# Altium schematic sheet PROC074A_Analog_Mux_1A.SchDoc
size 431 x 279 mm; Date: Not shown in title block; ApprovedBy: Not shown in title block; CheckedBy: Not shown in title block; Author: Not shown in title block; CompanyName: Not shown in title block; Engineer: Not shown in title block; Organization: Not shown in title block; Address1: Not shown in title block; Address2: Not shown in title block; Address3: Not shown in title block; Address4: Not shown in title block; DocumentNumber: 1; Revision: Use project parameter SCH_Rev; SheetNumber: 19; SheetTotal: 22; PageSetup: Record=PageOptions¦CenterHorizontal=True¦CenterVertical=True¦PrintScale=1.00¦XCorrection=1.00¦YCorrection=1.00¦PrintKind=0¦BorderSize=5000000¦LeftOffset=0¦BottomOffset=0¦Orientation=2¦PaperLength=1000¦PaperWidth=1000¦Scale=100¦PaperSource=15¦PrintQuality=600¦MediaType=1¦DitherType=10¦PaperKind=Letter¦PrintScaleMode=1
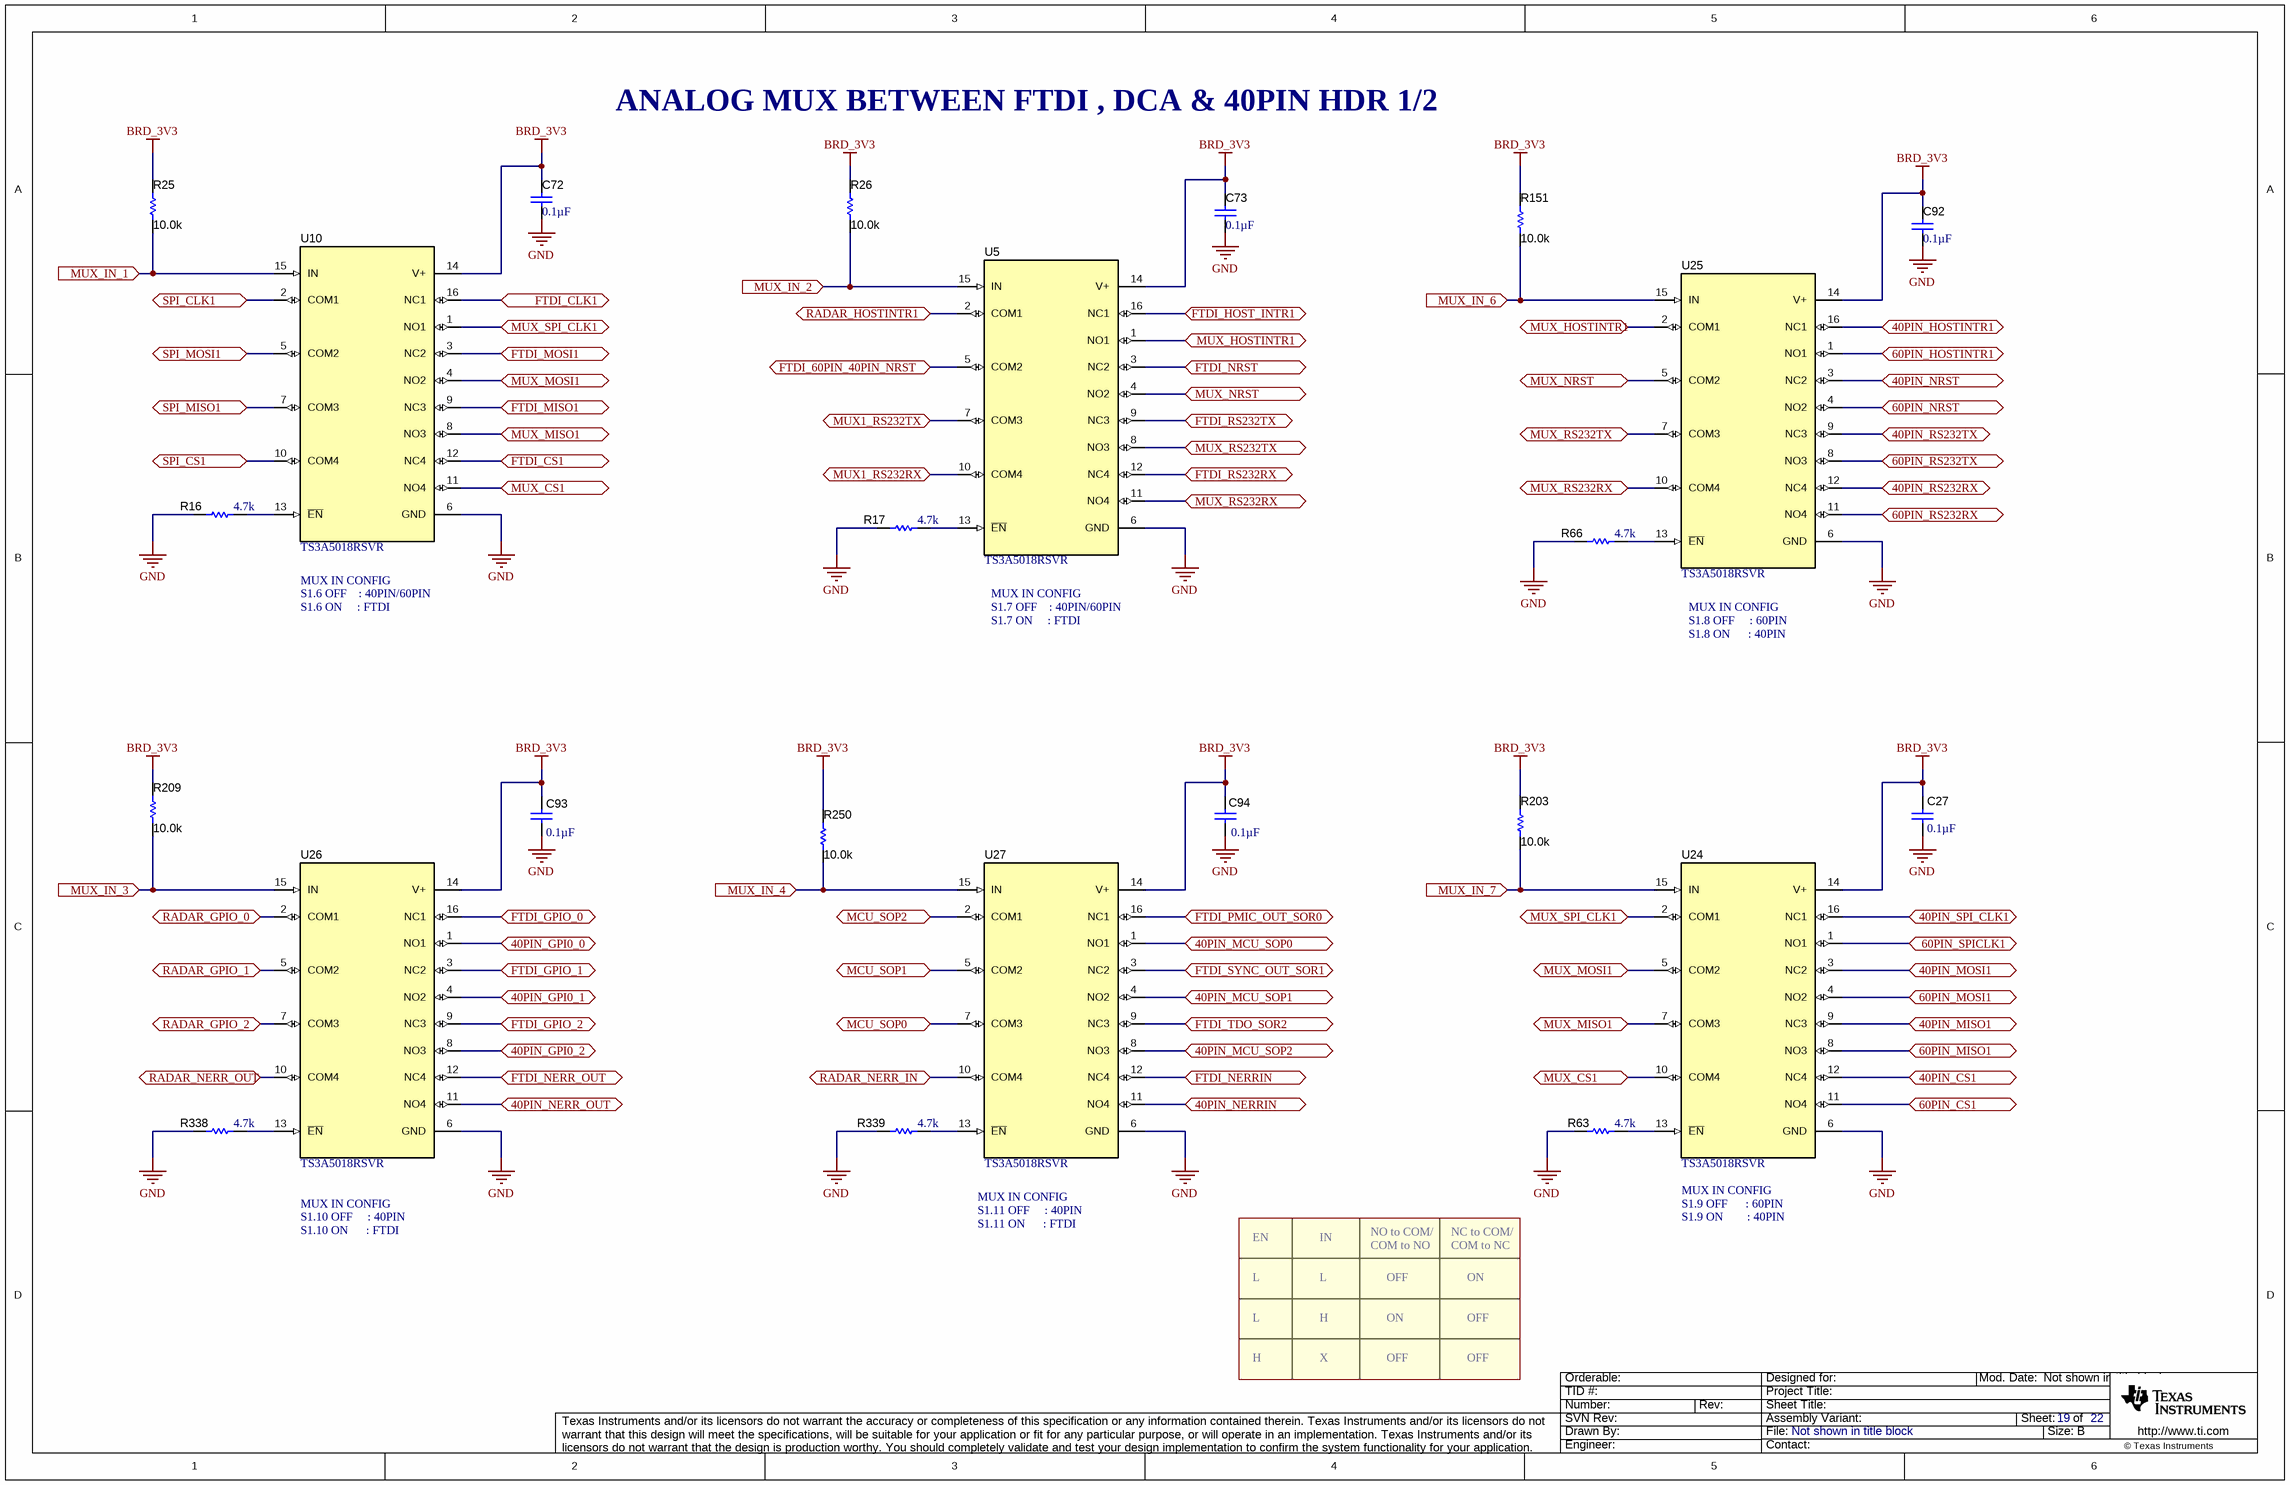
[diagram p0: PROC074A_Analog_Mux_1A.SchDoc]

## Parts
C27  ValueDisplayed: 0.1µF  [0402]  (hidden comment: C0402C104K8RACTU)
C72  ValueDisplayed: 0.1µF  [0402]  (hidden comment: C0402C104K8RACTU)
C73  ValueDisplayed: 0.1µF  [0402]  (hidden comment: C0402C104K8RACTU)
C92  ValueDisplayed: 0.1µF  [0402]  (hidden comment: C0402C104K8RACTU)
C93  ValueDisplayed: 0.1µF  [0402]  (hidden comment: C0402C104K8RACTU)
C94  ValueDisplayed: 0.1µF  [0402]  (hidden comment: C0402C104K8RACTU)
R16  ValueDisplayed: 4.7k  [0402]  (hidden comment: CRCW04024K70JNED)
R17  ValueDisplayed: 4.7k  [0402]  (hidden comment: CRCW04024K70JNED)
R25  ValueDisplayed: 10.0k  [0402L]  (hidden comment: CRCW040210K0FKED)
R26  ValueDisplayed: 10.0k  [0402L]  (hidden comment: CRCW040210K0FKED)
R63  ValueDisplayed: 4.7k  [0402]  (hidden comment: CRCW04024K70JNED)
R66  ValueDisplayed: 4.7k  [0402]  (hidden comment: CRCW04024K70JNED)
R151  ValueDisplayed: 10.0k  [0402L]  (hidden comment: CRCW040210K0FKED)
R203  ValueDisplayed: 10.0k  [0402L]  (hidden comment: CRCW040210K0FKED)
R209  ValueDisplayed: 10.0k  [0402L]  (hidden comment: CRCW040210K0FKED)
R250  ValueDisplayed: 10.0k  [0402L]  (hidden comment: CRCW040210K0FKED)
R338  ValueDisplayed: 4.7k  [0402]  (hidden comment: CRCW04024K70JNED)
R339  ValueDisplayed: 4.7k  [0402]  (hidden comment: CRCW04024K70JNED)
U5  TS3A5018RSVR  [RSV0016A]
U10  TS3A5018RSVR  [RSV0016A]
U24  TS3A5018RSVR  [RSV0016A]
U25  TS3A5018RSVR  [RSV0016A]
U26  TS3A5018RSVR  [RSV0016A]
U27  TS3A5018RSVR  [RSV0016A]

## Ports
40PIN_CS1, 40PIN_GPI0_0, 40PIN_GPI0_1, 40PIN_GPI0_2, 40PIN_HOSTINTR1, 40PIN_MCU_SOP0, 40PIN_MCU_SOP1, 40PIN_MCU_SOP2, 40PIN_MISO1, 40PIN_MOSI1, 40PIN_NERR_OUT, 40PIN_NERRIN, 40PIN_NRST, 40PIN_RS232RX, 40PIN_RS232TX, 40PIN_SPI_CLK1, 60PIN_CS1, 60PIN_HOSTINTR1, 60PIN_MISO1, 60PIN_MOSI1, 60PIN_NRST, 60PIN_RS232RX, 60PIN_RS232TX, 60PIN_SPICLK1, FTDI_60PIN_40PIN_NRST, FTDI_CLK1, FTDI_CS1, FTDI_GPIO_0, FTDI_GPIO_1, FTDI_GPIO_2, FTDI_HOST_INTR1, FTDI_MISO1, FTDI_MOSI1, FTDI_NERR_OUT, FTDI_NERRIN, FTDI_NRST, FTDI_PMIC_OUT_SOR0, FTDI_RS232RX, FTDI_RS232TX, FTDI_SYNC_OUT_SOR1, FTDI_TDO_SOR2, MCU_SOP0, MCU_SOP1, MCU_SOP2, MUX1_RS232RX, MUX1_RS232TX, MUX_CS1, MUX_HOSTINTR1, MUX_IN_1 (in), MUX_IN_2 (in), MUX_IN_3 (in), MUX_IN_4 (in), MUX_IN_6 (in), MUX_IN_7 (in), MUX_MISO1, MUX_MOSI1, MUX_NRST, MUX_RS232RX, MUX_RS232TX, MUX_SPI_CLK1, RADAR_GPIO_0, RADAR_GPIO_1, RADAR_GPIO_2, RADAR_HOSTINTR1, RADAR_NERR_IN, RADAR_NERR_OUT, SPI_CLK1, SPI_CS1, SPI_MISO1, SPI_MOSI1

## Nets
BRD_3V3: C27.1 C72.1 C73.1 C92.1 C93.1 C94.1 R25.2 R26.2 R151.2 R203.2 R209.2 R250.2 U5.14(V+) U10.14(V+) U24.14(V+) U25.14(V+) U26.14(V+) U27.14(V+)
GND: C27.2 C72.2 C73.2 C92.2 C93.2 C94.2 R16.1 R17.1 R63.1 R66.1 R338.1 R339.1 U5.6(GND) U10.6(GND) U24.6(GND) U25.6(GND) U26.6(GND) U27.6(GND)
40PIN_CS1: U24.12(NC4) ; port 40PIN_CS1
40PIN_GPI0_0: U26.1(NO1) ; port 40PIN_GPI0_0
40PIN_GPI0_1: U26.4(NO2) ; port 40PIN_GPI0_1
40PIN_GPI0_2: U26.8(NO3) ; port 40PIN_GPI0_2
40PIN_HOSTINTR1: U25.16(NC1) ; port 40PIN_HOSTINTR1
40PIN_MCU_SOP0: U27.1(NO1) ; port 40PIN_MCU_SOP0
40PIN_MCU_SOP1: U27.4(NO2) ; port 40PIN_MCU_SOP1
40PIN_MCU_SOP2: U27.8(NO3) ; port 40PIN_MCU_SOP2
40PIN_MISO1: U24.9(NC3) ; port 40PIN_MISO1
40PIN_MOSI1: U24.3(NC2) ; port 40PIN_MOSI1
40PIN_NERR_OUT: U26.11(NO4) ; port 40PIN_NERR_OUT
40PIN_NERRIN: U27.11(NO4) ; port 40PIN_NERRIN
40PIN_NRST: U25.3(NC2) ; port 40PIN_NRST
40PIN_RS232RX: U25.12(NC4) ; port 40PIN_RS232RX
40PIN_RS232TX: U25.9(NC3) ; port 40PIN_RS232TX
40PIN_SPI_CLK1: U24.16(NC1) ; port 40PIN_SPI_CLK1
60PIN_CS1: U24.11(NO4) ; port 60PIN_CS1
60PIN_HOSTINTR1: U25.1(NO1) ; port 60PIN_HOSTINTR1
60PIN_MISO1: U24.8(NO3) ; port 60PIN_MISO1
60PIN_MOSI1: U24.4(NO2) ; port 60PIN_MOSI1
60PIN_NRST: U25.4(NO2) ; port 60PIN_NRST
60PIN_RS232RX: U25.11(NO4) ; port 60PIN_RS232RX
60PIN_RS232TX: U25.8(NO3) ; port 60PIN_RS232TX
60PIN_SPICLK1: U24.1(NO1) ; port 60PIN_SPICLK1
FTDI_60PIN_40PIN_NRST: U5.5(COM2) ; port FTDI_60PIN_40PIN_NRST
FTDI_CLK1: U10.16(NC1) ; port FTDI_CLK1
FTDI_CS1: U10.12(NC4) ; port FTDI_CS1
FTDI_GPIO_0: U26.16(NC1) ; port FTDI_GPIO_0
FTDI_GPIO_1: U26.3(NC2) ; port FTDI_GPIO_1
FTDI_GPIO_2: U26.9(NC3) ; port FTDI_GPIO_2
FTDI_HOST_INTR1: U5.16(NC1) ; port FTDI_HOST_INTR1
FTDI_MISO1: U10.9(NC3) ; port FTDI_MISO1
FTDI_MOSI1: U10.3(NC2) ; port FTDI_MOSI1
FTDI_NERR_OUT: U26.12(NC4) ; port FTDI_NERR_OUT
FTDI_NERRIN: U27.12(NC4) ; port FTDI_NERRIN
FTDI_NRST: U5.3(NC2) ; port FTDI_NRST
FTDI_PMIC_OUT_SOR0: U27.16(NC1) ; port FTDI_PMIC_OUT_SOR0
FTDI_RS232RX: U5.12(NC4) ; port FTDI_RS232RX
FTDI_RS232TX: U5.9(NC3) ; port FTDI_RS232TX
FTDI_SYNC_OUT_SOR1: U27.3(NC2) ; port FTDI_SYNC_OUT_SOR1
FTDI_TDO_SOR2: U27.9(NC3) ; port FTDI_TDO_SOR2
MCU_SOP0: U27.7(COM3) ; port MCU_SOP0
MCU_SOP1: U27.5(COM2) ; port MCU_SOP1
MCU_SOP2: U27.2(COM1) ; port MCU_SOP2
MUX1_RS232RX: U5.10(COM4) ; port MUX1_RS232RX
MUX1_RS232TX: U5.7(COM3) ; port MUX1_RS232TX
MUX_CS1: U10.11(NO4) U24.10(COM4) ; port MUX_CS1
MUX_HOSTINTR1: U5.1(NO1) U25.2(COM1) ; port MUX_HOSTINTR1
MUX_IN_1: R25.1 U10.15(IN) ; port MUX_IN_1
MUX_IN_2: R26.1 U5.15(IN) ; port MUX_IN_2
MUX_IN_3: R209.1 U26.15(IN) ; port MUX_IN_3
MUX_IN_4: R250.1 U27.15(IN) ; port MUX_IN_4
MUX_IN_6: R151.1 U25.15(IN) ; port MUX_IN_6
MUX_IN_7: R203.1 U24.15(IN) ; port MUX_IN_7
MUX_MISO1: U10.8(NO3) U24.7(COM3) ; port MUX_MISO1
MUX_MOSI1: U10.4(NO2) U24.5(COM2) ; port MUX_MOSI1
MUX_NRST: U5.4(NO2) U25.5(COM2) ; port MUX_NRST
MUX_RS232RX: U5.11(NO4) U25.10(COM4) ; port MUX_RS232RX
MUX_RS232TX: U5.8(NO3) U25.7(COM3) ; port MUX_RS232TX
MUX_SPI_CLK1: U10.1(NO1) U24.2(COM1) ; port MUX_SPI_CLK1
RADAR_GPIO_0: U26.2(COM1) ; port RADAR_GPIO_0
RADAR_GPIO_1: U26.5(COM2) ; port RADAR_GPIO_1
RADAR_GPIO_2: U26.7(COM3) ; port RADAR_GPIO_2
RADAR_HOSTINTR1: U5.2(COM1) ; port RADAR_HOSTINTR1
RADAR_NERR_IN: U27.10(COM4) ; port RADAR_NERR_IN
RADAR_NERR_OUT: U26.10(COM4) ; port RADAR_NERR_OUT
SPI_CLK1: U10.2(COM1) ; port SPI_CLK1
SPI_CS1: U10.10(COM4) ; port SPI_CS1
SPI_MISO1: U10.7(COM3) ; port SPI_MISO1
SPI_MOSI1: U10.5(COM2) ; port SPI_MOSI1
NetR16_2: R16.2 U10.13(~{EN})
NetR17_2: R17.2 U5.13(~{EN})
NetR63_2: R63.2 U24.13(~{EN})
NetR66_2: R66.2 U25.13(~{EN})
NetR338_2: R338.2 U26.13(~{EN})
NetR339_2: R339.2 U27.13(~{EN})

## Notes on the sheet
- ANALOG MUX BETWEEN FTDI , DCA & 40PIN HDR 1/2
- MUX IN CONFIG
- S1.6 OFF    : 40PIN/60PIN
- S1.6 ON     : FTDI
- S1.7 OFF    : 40PIN/60PIN
- S1.7 ON     : FTDI
- S1.8 OFF     : 60PIN
- S1.8 ON      : 40PIN
- S1.10 OFF     : 40PIN
- S1.10 ON      : FTDI
- S1.11 OFF     : 40PIN
- S1.11 ON      : FTDI
- EN
- IN
- NO to COM/
- NC to COM/
- S1.9 OFF      : 60PIN
- S1.9 ON        : 40PIN
- L
- COM to NO
- OFF
- COM to NC
- ON
- H
- X

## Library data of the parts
C27 C72 C73 C92-C94 = CMP-0078241-1: CAP, CERM, 0.1 µF, 10 V,+/- 10%, X7R, 0402; Manufacturer: Kemet; TaMin_C: -55°C; Polarized: N; SizeAreaWB_mm2: 3; U/M: EA; Value: 0.1uF; TaMax_C: 125°C; SizeZ_mm: 0.6; SizeX_mm: 1; SizeY_mm: 0.5; Value2: 10V; CompType: Capacitor; Cap_F: 100nF; AEC Category: Q200
R16 R17 R63 R66 R338 R339 = CMP-0026938-5: RES, 4.7 k, 5%, 0.063 W, AEC-Q200 Grade 0, 0402; Manufacturer: Vishay-Dale; Power_W: 63mW; TempCo: 200 ppm/C; Value_Code: 4k70; Value: 4.7k; EIA_Code: E24; SizeX_mm: 1; SizeY_mm: 0.5; SizeZ_mm: 0.6; Value2: 0.063W; AEC Qualified: Y; VDC_V: 50V; AEC Category: Q200; AEC Grade: 0
R25 R26 R151 R203 R209 R250 = CMP-0025958-2: RES, 10.0 k, 1%, 0.063 W, 0402; Manufacturer: Vishay-Dale; Power_W: 63mW; TempCo: 100 ppm/C; Value_Code: 10k0; U/M: EA; Value: 10.0k; EIA_Code: E96; Res_ohm: 10k; SizeX_mm: 1; SizeY_mm: 0.5; SizeZ_mm: 0.6; Value2: 0.063W; VDC_V: 50V; AEC Category: Q200
U5 U10 U24-U27 = CMP-0067415-1: 10-Ohm Quad SPDT Analog Switch, RSV0016A (UQFN-16); Alternate Manufacturer: Texas Instruments; SizeAreaWB_mm2: 10.08; U/M: EA; SizeZ_mm: 0.55; SizeX_mm: 1.8; SizeY_mm: 2.6; SizeArea_mm2: 4.68; CompType: IC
